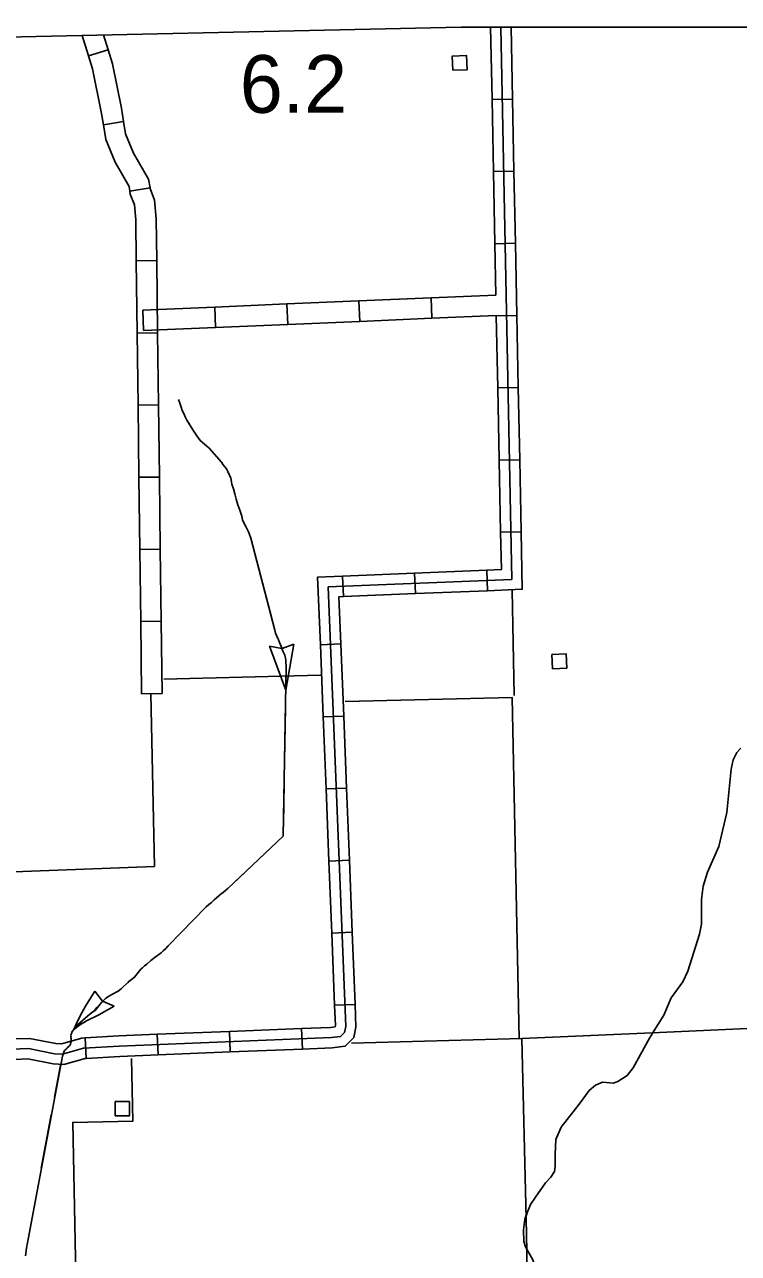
# Model space of a CAD drawing. Extents: x 1084508 to 1142749, y 1057638 to 1093403.
# Drawn here: x 1091437 to 1093076, y 1084838 to 1087661 of the extents above; entities that cross this region are included whole.
import ezdxf

# ---------------------------------------------------------------- set-up
doc = ezdxf.new("R2010")
doc.units = 0
for name, color, linetype in [('Level 10', 7, 'Continuous'), ('Level 2', 7, 'Continuous'), ('Level 32', 7, 'Continuous'), ('Level 35', 7, 'Continuous'), ('Level 43', 7, 'Continuous'), ('Level 48', 7, 'Continuous'), ('Level 5', 7, 'Continuous'), ('Level 56', 7, 'Continuous'), ('Level 7', 7, 'Continuous')]:
    doc.layers.add(name, color=color, linetype=linetype)

msp = doc.modelspace()

# ---------------------------------------------------------------- linework, layer by layer
at = {"layer": 'Level 10'}
msp.add_lwpolyline([(1093881.4, 1087660.9), (1093519.5, 1087654.6), (1092439.5, 1087655.1), (1091184.1, 1087627.6), (1090798.1, 1087623.3)], dxfattribs=at)
at = {"layer": 'Level 2'}
msp.add_lwpolyline([(1093449.8, 1085370.6), (1092878.3, 1085344.7), (1092578.4, 1085331.3), (1092588.9, 1084918.3), (1092590.1, 1084843.3), (1092591.2, 1084775.8), (1092615.4, 1083619.6)], dxfattribs=at)
at = {"layer": 'Level 32'}
for p, q in [((1092507, 1087654.6), (1092554.1, 1087655.5)), ((1092530.6, 1087655), (1092555.7, 1086386.1)), ((1091628.5, 1087603.2), (1091583.5, 1087589)), ((1092510.3, 1087488.9), (1092557.4, 1087489.8)), ((1091664, 1087438.1), (1091617.6, 1087430.5)), ((1092513.6, 1087323.2), (1092560.6, 1087324.1)), ((1091724.8, 1087286), (1091678.4, 1087278)), ((1092516.9, 1087157.5), (1092563.9, 1087158.4)), ((1091740.3, 1087118.6), (1091693.2, 1087118)), ((1092372.3, 1086986.1), (1092370.3, 1087033.2)), ((1091709.9, 1086957.9), (1091707.9, 1087004.9)), ((1091875.5, 1086964.9), (1091873.5, 1087012)), ((1092041.1, 1086972), (1092039.1, 1087019)), ((1092206.7, 1086979.1), (1092204.7, 1087026.1)), ((1092520.1, 1086991.8), (1092567.2, 1086992.7)), ((1091742.3, 1086952.9), (1091695.2, 1086952.3)), ((1092523.4, 1086826.1), (1092570.5, 1086827)), ((1091744.3, 1086787.2), (1091697.3, 1086786.6)), ((1092526.7, 1086660.4), (1092573.8, 1086661.3)), ((1091746.4, 1086621.4), (1091699.3, 1086620.9)), ((1092530, 1086494.7), (1092577, 1086495.6)), ((1091748.4, 1086455.7), (1091701.3, 1086455.2)), ((1092166.9, 1086393.9), (1092168.8, 1086346.8)), ((1092332.5, 1086400.6), (1092334.4, 1086353.6)), ((1092498.1, 1086407.3), (1092500, 1086360.3)), ((1091750.4, 1086290), (1091703.3, 1086289.4)), ((1092115.9, 1086236.1), (1092162.9, 1086238)), ((1091752.4, 1086124.3), (1091705.3, 1086123.7)), ((1092122.4, 1086070.5), (1092169.5, 1086072.4)), ((1092129, 1085904.9), (1092176, 1085906.8)), ((1092135.5, 1085739.3), (1092182.6, 1085741.2)), ((1092142, 1085573.7), (1092189.1, 1085575.6)), ((1092148.6, 1085408.1), (1092195.6, 1085410)), ((1091741.5, 1085341.2), (1091743.4, 1085294.1)), ((1091907.1, 1085347.8), (1091909, 1085300.7)), ((1092072.7, 1085354.4), (1092074.6, 1085307.4)), ((1091575.5, 1085332.8), (1091578.4, 1085285.8))]:
    msp.add_line(p, q, dxfattribs=at)
for points in [[(1092507, 1087654.6), (1092510.3, 1087488.9)], [(1092554.1, 1087655.5), (1092557.4, 1087489.8)], [(1091583.5, 1087589), (1091568.7, 1087636)], [(1091628.5, 1087603.2), (1091617.8, 1087637.1)], [(1091664, 1087438.1), (1091659, 1087469.1), (1091638.7, 1087570.6), (1091628.5, 1087603.2)], [(1091617.6, 1087430.5), (1091612.6, 1087460.7), (1091593, 1087558.9), (1091583.5, 1087589)], [(1092510.3, 1087488.9), (1092513.6, 1087323.2)], [(1092557.4, 1087489.8), (1092560.6, 1087324.1)], [(1091678.4, 1087278), (1091676.5, 1087289.2), (1091644.5, 1087344.9), (1091623, 1087397.2), (1091617.6, 1087430.5)], [(1091724.8, 1087286), (1091721.5, 1087305.4), (1091686.9, 1087365.7), (1091668.6, 1087410.1), (1091664, 1087438.1)], [(1092513.6, 1087323.2), (1092516.9, 1087157.5)], [(1092560.6, 1087324.1), (1092563.9, 1087158.4)], [(1091693.2, 1087118), (1091692.1, 1087212.3), (1091689.1, 1087246.8), (1091679.5, 1087271.6), (1091678.4, 1087278)], [(1091740.3, 1087118.6), (1091739.1, 1087214.6), (1091735.4, 1087257.5), (1091725.1, 1087284.2), (1091724.8, 1087286)], [(1092516.9, 1087157.5), (1092519.2, 1087039.5)], [(1092563.9, 1087158.4), (1092567.2, 1086992.7)], [(1091695.2, 1086952.3), (1091693.2, 1087118)], [(1091742.3, 1086952.9), (1091740.3, 1087118.6)], [(1092204.7, 1087026.1), (1092370.3, 1087033.2)], [(1092370.3, 1087033.2), (1092519.2, 1087039.5)], [(1091707.9, 1087004.9), (1091873.5, 1087012)], [(1091873.5, 1087012), (1092039.1, 1087019)], [(1092039.1, 1087019), (1092204.7, 1087026.1)], [(1092041.1, 1086972), (1092206.7, 1086979.1)], [(1092206.7, 1086979.1), (1092372.3, 1086986.1)], [(1092372.3, 1086986.1), (1092520.1, 1086992.4)], [(1092520.1, 1086992.4), (1092520.1, 1086991.8)], [(1092520.1, 1086991.8), (1092523.4, 1086826.1)], [(1092567.2, 1086992.7), (1092570.5, 1086827)], [(1091697.3, 1086786.6), (1091695.2, 1086952.3)], [(1091709.9, 1086957.9), (1091875.5, 1086964.9)], [(1091744.3, 1086787.2), (1091742.3, 1086952.9)], [(1091875.5, 1086964.9), (1092041.1, 1086972)], [(1092523.4, 1086826.1), (1092526.7, 1086660.4)], [(1092570.5, 1086827), (1092573.8, 1086661.3)], [(1091699.3, 1086620.9), (1091697.3, 1086786.6)], [(1091746.4, 1086621.4), (1091744.3, 1086787.2)], [(1092526.7, 1086660.4), (1092530, 1086494.7)], [(1092573.8, 1086661.3), (1092577, 1086495.6)], [(1091701.3, 1086455.2), (1091699.3, 1086620.9)], [(1091748.4, 1086455.7), (1091746.4, 1086621.4)], [(1092530, 1086494.7), (1092531.7, 1086408.7), (1092498.1, 1086407.3)], [(1092577, 1086495.6), (1092579.7, 1086363.5), (1092500, 1086360.3)], [(1091703.3, 1086289.4), (1091701.3, 1086455.2)], [(1091750.4, 1086290), (1091748.4, 1086455.7)], [(1092555.7, 1086386.1), (1092134.2, 1086369), (1092174.1, 1085359.5), (1092171.3, 1085345.4), (1092162.3, 1085336.1), (1092141.3, 1085333.6), (1091654.2, 1085314.1)], [(1092166.9, 1086393.9), (1092109.7, 1086391.6), (1092115.9, 1086236.1)], [(1092332.5, 1086400.6), (1092166.9, 1086393.9)], [(1092498.1, 1086407.3), (1092332.5, 1086400.6)], [(1092500, 1086360.3), (1092334.4, 1086353.6)], [(1092168.8, 1086346.8), (1092158.6, 1086346.4), (1092162.9, 1086238)], [(1092334.4, 1086353.6), (1092168.8, 1086346.8)], [(1091705.3, 1086123.7), (1091703.3, 1086289.4)], [(1091752.4, 1086124.3), (1091750.4, 1086290)], [(1092115.9, 1086236.1), (1092122.4, 1086070.5)], [(1092162.9, 1086238), (1092169.5, 1086072.4)], [(1092122.4, 1086070.5), (1092129, 1085904.9)], [(1092169.5, 1086072.4), (1092176, 1085906.8)], [(1092129, 1085904.9), (1092135.5, 1085739.3)], [(1092176, 1085906.8), (1092182.6, 1085741.2)], [(1092135.5, 1085739.3), (1092142, 1085573.7)], [(1092182.6, 1085741.2), (1092189.1, 1085575.6)], [(1092142, 1085573.7), (1092148.6, 1085408.1)], [(1092189.1, 1085575.6), (1092195.6, 1085410)], [(1092148.6, 1085408.1), (1092150.4, 1085361.3), (1092149.9, 1085358.4), (1092139.4, 1085357.1), (1092072.7, 1085354.4)], [(1092195.6, 1085410), (1092197.7, 1085357.6), (1092193, 1085334), (1092173.3, 1085313.8), (1092143.2, 1085310.1), (1092074.6, 1085307.4)], [(1091741.5, 1085341.2), (1091653, 1085337.6), (1091575.5, 1085332.8)], [(1091907.1, 1085347.8), (1091741.5, 1085341.2)], [(1092072.7, 1085354.4), (1091907.1, 1085347.8)], [(1091575.5, 1085332.8), (1091568, 1085332.3), (1091521.1, 1085319.3), (1091508.1, 1085319.9), (1091447.7, 1085331.9), (1091413.3, 1085330.5)], [(1091654.2, 1085314.1), (1091571.9, 1085309)], [(1091571.9, 1085309), (1091523.8, 1085295.6), (1091505.2, 1085296.4), (1091445.8, 1085308.3), (1090928.2, 1085288.1), (1089722.3, 1085244.4), (1089684.6, 1085237), (1089659.7, 1085226.1), (1089609.5, 1085184.3), (1089602.5, 1085178.3)], [(1091578.4, 1085285.8), (1091575.9, 1085285.6), (1091526.5, 1085271.9), (1091502.4, 1085273), (1091444, 1085284.6), (1091415.2, 1085283.5)], [(1091743.4, 1085294.1), (1091655.4, 1085290.6), (1091578.4, 1085285.8)], [(1091909, 1085300.7), (1091743.4, 1085294.1)], [(1092074.6, 1085307.4), (1091909, 1085300.7)]]:
    msp.add_lwpolyline(points, dxfattribs=at)
at = {"layer": 'Level 35'}
for points in [[(1093005.4, 1085713.7), (1093031.1, 1085773), (1093049.3, 1085850.5), (1093059.3, 1085950.1), (1093064.3, 1085971.4), (1093072.3, 1085988.8), (1093081.6, 1085998.4)], [(1092878.7, 1085344), (1092904.8, 1085385), (1092921.6, 1085424.9), (1092948.2, 1085461.5), (1092959.7, 1085486), (1092987, 1085571.2), (1092991.3, 1085594.4), (1092991.6, 1085650.6), (1092995.3, 1085681.4), (1093005.4, 1085713.7)], [(1092610.3, 1084967.3), (1092633.4, 1084999.9), (1092645.4, 1085012.8), (1092653.9, 1085026.1), (1092655.6, 1085037.8), (1092655.6, 1085065), (1092656.9, 1085099.7), (1092668.8, 1085127.8), (1092710.5, 1085180.8), (1092733.6, 1085212.1), (1092747.5, 1085224.1), (1092764.2, 1085231.2), (1092788.8, 1085229.2), (1092799.1, 1085232.5), (1092820.4, 1085246.7), (1092834.4, 1085264.1), (1092871.6, 1085332.7), (1092879.2, 1085344.7)], [(1092588.7, 1084925.4), (1092598.5, 1084950.6), (1092610.3, 1084967.3)], [(1092591.1, 1084845.7), (1092587.1, 1084852.6), (1092583.4, 1084865.1), (1092582.8, 1084892.2), (1092585.5, 1084916.9), (1092589.8, 1084928.1)], [(1092590.1, 1084847.4), (1092587.1, 1084852.6), (1092583.4, 1084865.1), (1092582.8, 1084892.2), (1092585.5, 1084916.9), (1092588.7, 1084925.4)], [(1092591.1, 1084776.7), (1092605.4, 1084795.7), (1092607.6, 1084811), (1092603.9, 1084823.4), (1092590.1, 1084847.4)]]:
    msp.add_lwpolyline(points, dxfattribs=at)
at = {"layer": 'Level 43'}
for p, q in [((1091999.4, 1086232.6), (1092027.6, 1086227.7)), ((1092036.5, 1086131.5), (1091999.4, 1086232.6)), ((1092028, 1086227.8), (1092054.9, 1086237.6)), ((1092054.9, 1086237.6), (1092036.5, 1086131.5)), ((1091598, 1085440.1), (1091615.4, 1085417.3)), ((1091615.7, 1085417.1), (1091642.1, 1085406))]:
    msp.add_line(p, q, dxfattribs=at)
for points in [[(1091790.4, 1086799.4), (1091792.5, 1086793.2), (1091794, 1086788.9), (1091796.2, 1086781.7), (1091798.7, 1086774.3), (1091802.2, 1086767.2), (1091805.7, 1086759.7), (1091809.5, 1086752), (1091819.3, 1086736.4), (1091824.5, 1086727.5), (1091832.2, 1086716.5), (1091840.2, 1086705.5), (1091850.1, 1086696.8), (1091860.9, 1086687.8), (1091889.1, 1086655.3), (1091893, 1086649.3), (1091900.7, 1086640), (1091903.2, 1086634.2), (1091910.2, 1086618.7), (1091913, 1086605), (1091916.1, 1086594.1), (1091919.4, 1086583.2), (1091922.8, 1086570.4), (1091926.5, 1086557.3), (1091930.8, 1086545.5), (1091935.6, 1086531.5), (1091937.5, 1086523.4), (1091940.7, 1086515.1), (1091944.5, 1086507.7), (1091947.2, 1086503), (1091950.7, 1086495.6), (1091952.8, 1086491.6), (1091956.4, 1086481.4), (1092011.6, 1086269.9), (1092013.1, 1086263.1), (1092016, 1086255.6), (1092019.5, 1086247.3), (1092022, 1086241.4), (1092026.5, 1086230.6), (1092029.1, 1086223.7), (1092030.8, 1086220), (1092032.6, 1086215.1), (1092034, 1086212), (1092035.1, 1086208.2), (1092035.9, 1086205.1)], [(1091790.4, 1086799.4), (1091792.5, 1086793.2), (1091794, 1086788.9), (1091796.2, 1086781.7), (1091798.7, 1086774.3), (1091802.2, 1086767.2), (1091805.7, 1086759.7), (1091809.5, 1086752), (1091815.3, 1086742.8)], [(1091838.2, 1086708.3), (1091840.2, 1086705.5), (1091850.1, 1086696.8), (1091860.9, 1086687.8), (1091889.1, 1086655.3), (1091893, 1086649.3), (1091900.7, 1086640), (1091903.2, 1086634.2), (1091910.2, 1086618.7), (1091911.8, 1086610.8)], [(1091922.7, 1086570.9), (1091922.8, 1086570.4), (1091926.5, 1086557.3), (1091930.8, 1086545.5), (1091935.6, 1086531.5), (1091937.5, 1086523.4), (1091940.7, 1086515.1), (1091944.5, 1086507.7), (1091947.2, 1086503), (1091950.7, 1086495.6), (1091952.8, 1086491.6), (1091956.4, 1086481.4), (1091963.5, 1086453.9)], [(1091974, 1086413.8), (1092005.4, 1086293.6)], [(1092016.7, 1086253.8), (1092019.5, 1086247.3), (1092022, 1086241.4), (1092026.5, 1086230.6), (1092029.1, 1086223.7), (1092030.8, 1086220), (1092032.6, 1086215.1), (1092034, 1086212), (1092035.1, 1086208.2), (1092035.9, 1086205.1), (1092036.5, 1086201.3), (1092036.5, 1086197.6), (1092037, 1086194.4), (1092037.3, 1086187.8), (1092036.4, 1086133.3)], [(1092035.9, 1086205.1), (1092036.6, 1086202), (1092036.5, 1086197.6), (1092037, 1086194.4), (1092037.3, 1086187.8), (1092030.7, 1085796.5), (1091903.1, 1085676.1), (1091899.4, 1085673.4), (1091893.7, 1085668.1), (1091888.2, 1085663.8), (1091882.8, 1085659.1), (1091876.7, 1085653.8), (1091872.2, 1085649.8), (1091865.8, 1085644.1), (1091860, 1085639.7), (1091853.4, 1085634.1), (1091766.8, 1085544.6), (1091760.8, 1085538), (1091755.3, 1085533.3), (1091750.2, 1085528.7), (1091744.7, 1085524.6), (1091742, 1085522.3), (1091736.5, 1085518.6), (1091726.5, 1085510.9), (1091717.1, 1085502.5), (1091712.3, 1085498.2), (1091707.4, 1085493.9), (1091703.8, 1085490.6), (1091697.5, 1085483), (1091689.2, 1085472.2), (1091682.2, 1085466.9), (1091676.4, 1085462.2), (1091670.4, 1085456.9), (1091662.2, 1085449.5), (1091658.9, 1085446.2), (1091654.7, 1085442.6), (1091651.3, 1085440.5), (1091645.8, 1085437.1), (1091640.3, 1085434), (1091635.7, 1085431.6), (1091630.7, 1085428.8), (1091628, 1085427.1), (1091624.6, 1085424.8), (1091622.2, 1085423.1), (1091620.1, 1085421.1), (1091617.1, 1085418.4), (1091613.7, 1085415.1), (1091609.9, 1085410.5), (1091602.2, 1085400.1), (1091598.6, 1085396.1), (1091593.7, 1085392.7), (1091589.7, 1085389.7), (1091586.4, 1085387.4), (1091580.9, 1085382.7), (1091553.1, 1085358.7), (1091550.2, 1085353.2), (1091546.9, 1085348.6), (1091545.1, 1085346.3), (1091544.9, 1085344.4), (1091543.8, 1085341.5), (1091543.2, 1085339), (1091543.3, 1085337.4), (1091543.1, 1085335.2), (1091543.2, 1085333.3), (1091543.3, 1085331.4), (1091543.4, 1085328), (1091543.3, 1085324.8), (1091543.1, 1085322.3), (1091542.3, 1085318.4), (1091540.5, 1085315.8), (1091539.3, 1085314.8), (1091538.4, 1085313.5), (1091535.4, 1085310.9), (1091533.6, 1085309.2), (1091531.8, 1085307.2), (1091529.7, 1085305.2), (1091528.2, 1085303.9), (1091526.8, 1085300.1), (1091523.4, 1085291.1), (1091440.7, 1084850.2), (1091438.4, 1084832.1)], [(1092035.7, 1086091.9), (1092033.6, 1085967.6)], [(1092032.9, 1085926.2), (1092031.9, 1085864.1)], [(1092031.9, 1085864.1), (1092030.8, 1085801.9)], [(1092004.5, 1085771.8), (1091914.1, 1085686.5)], [(1091882.9, 1085659.2), (1091882.8, 1085659.1), (1091876.7, 1085653.8), (1091872.2, 1085649.8), (1091865.8, 1085644.1), (1091860, 1085639.7), (1091853.4, 1085634.1), (1091794, 1085572.7)], [(1091765.2, 1085542.8), (1091760.8, 1085538), (1091755.3, 1085533.3), (1091750.2, 1085528.7), (1091744.7, 1085524.6), (1091742, 1085522.3), (1091736.5, 1085518.6), (1091726.5, 1085510.9), (1091717.1, 1085502.5), (1091712.3, 1085498.2), (1091707.4, 1085493.9), (1091703.8, 1085490.6), (1091697.5, 1085483), (1091689.2, 1085472.2), (1091682.2, 1085466.9), (1091676.4, 1085462.2), (1091673.6, 1085459.6)], [(1091598, 1085440.1), (1091576.8, 1085405.6), (1091564.6, 1085383.4), (1091555.7, 1085366), (1091549.4, 1085352.2)], [(1091641, 1085434.4), (1091640.3, 1085434), (1091635.7, 1085431.6), (1091630.7, 1085428.8), (1091628, 1085427.1), (1091624.6, 1085424.8), (1091622.2, 1085423.1), (1091620.1, 1085421.1), (1091617.1, 1085418.4), (1091613.7, 1085415.1), (1091609.9, 1085410.5), (1091602.7, 1085402.5), (1091598.7, 1085398.4), (1091593.4, 1085393.2), (1091589.7, 1085390.3), (1091586.4, 1085387.4), (1091580.9, 1085382.7), (1091554, 1085357.9), (1091550.2, 1085353.2), (1091549.5, 1085352.2)], [(1091642.1, 1085406), (1091606.8, 1085386), (1091579, 1085372), (1091563.1, 1085362.3), (1091549.4, 1085352.2)], [(1091519.5, 1085270.2), (1091505.7, 1085196.6)], [(1091498, 1085155.9), (1091486.6, 1085094.8)], [(1091486.6, 1085094.8), (1091475.1, 1085033.8)], [(1091467.5, 1084993), (1091444.6, 1084870.9)]]:
    msp.add_lwpolyline(points, dxfattribs=at)
at = {"layer": 'Level 5'}
for points in [[(1092556.2, 1086361.3), (1092561.4, 1086119.2)], [(1092187.4, 1085321), (1092578.4, 1085331.3)]]:
    msp.add_lwpolyline(points, dxfattribs=at)
at = {"layer": 'Level 56'}
for points in [[(1092420.3, 1087556), (1092419, 1087588.6), (1092451.8, 1087589.8), (1092453, 1087557.2)], [(1092649.3, 1086181.1), (1092647.8, 1086213.7), (1092680.5, 1086215.3), (1092682, 1086182.6)], [(1091644.8, 1085153.8), (1091644.8, 1085186.5), (1091677.6, 1085186.5), (1091677.6, 1085153.8)]]:
    msp.add_lwpolyline(points, close=True, dxfattribs=at)
at = {"layer": 'Level 7'}
for points in [[(1091756.3, 1086157), (1092116.4, 1086166.6)], [(1090947.5, 1085696.8), (1091734.9, 1085727.1), (1091726.7, 1086123.1)], [(1092173.2, 1086105.6), (1092556.3, 1086115), (1092572.8, 1085330.7)], [(1091906.2, 1084059.6), (1092184.1, 1084067.5), (1092177.9, 1084486.4), (1091560.5, 1084476.3), (1091547.3, 1085138.8), (1091684.9, 1085141.6), (1091682, 1085285.6)]]:
    msp.add_lwpolyline(points, dxfattribs=at)

# ---------------------------------------------------------------- texts
at = {"layer": 'Level 48'}
msp.add_text('6.2', height=132.58, dxfattribs=at).set_placement((1091931, 1087458.2))

doc.saveas('drawing.dxf')
